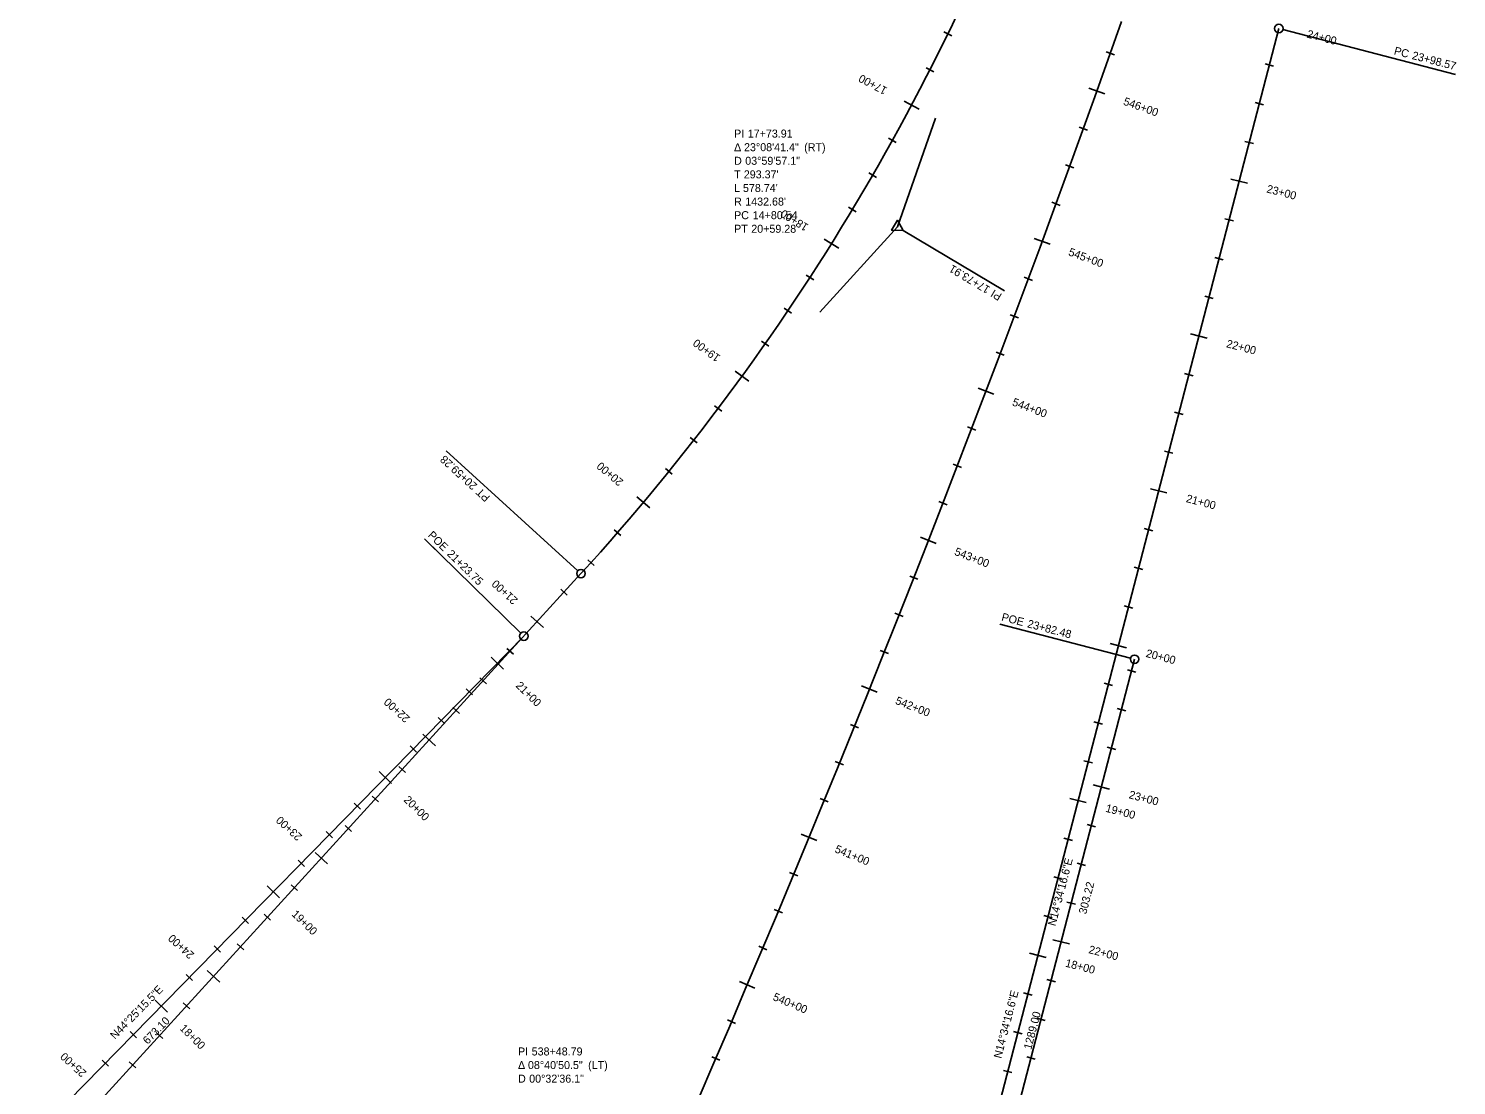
# Model space of a CAD drawing. Extents: x 2300830 to 2307917, y 756066 to 766359.
# Drawn here: x 2303759 to 2304651, y 762760 to 763421 of the extents above; entities that cross this region are included whole.
import ezdxf

# ---------------------------------------------------------------- set-up
doc = ezdxf.new("R2010")
doc.units = 0
for name, color, linetype in [('Default', 7, 'Continuous'), ('Draft_Bearing Label', 7, 'Continuous'), ('Draft_Curve Data Label', 7, 'Continuous'), ('Draft_Station Cardinal Lines', 7, 'Continuous'), ('Draft_Station Cardinal Points', 7, 'Continuous'), ('Draft_Station Labels Major', 7, 'Continuous'), ('Draft_Station Ticks Major', 7, 'Continuous'), ('Draft_Station Ticks Minor', 7, 'Continuous'), ('Geom_Baseline', 7, 'Continuous')]:
    doc.layers.add(name, color=color, linetype=linetype)

msp = doc.modelspace()

# ---------------------------------------------------------------- linework, layer by layer
at = {"layer": 'Default'}
for p, q in [((2304215.74, 762173.16), (2304540.03, 763420.7)), ((2304103.9, 763079.98), (2303443.21, 762356.01)), ((2303597.11, 762560.16), (2304068.23, 763040.89)), ((2304373.62, 762732.97), (2304449.9, 763026.43))]:
    msp.add_line(p, q, dxfattribs=at)
for centre, radius, start, end in [((2303045.65, 764045.73), 1432.68, 317.61666, 340.7615), ((2294501.04, 766942.01), 10544.55, 331.835697, 340.516399)]:
    msp.add_arc(centre, radius, start, end, dxfattribs=at)
at = {"layer": 'Draft_Station Cardinal Lines'}
for p, q in [((2304542.61, 763420.03), (2304650.36, 763392.02)), ((2304301.65, 763296.67), (2304325.38, 763364.65)), ((2304301.65, 763296.67), (2304253.12, 763243.49)), ((2304305.26, 763294.52), (2304368.64, 763256.72)), ((2304101.93, 763081.78), (2304019.69, 763156.82))]:
    msp.add_line(p, q, dxfattribs=at)
msp.add_lwpolyline([(2304305.22, 763294.55), (2304301.71, 763300.83), (2304298.02, 763294.65)], close=True, dxfattribs=at)
at = {"layer": 'Draft_Station Cardinal Points'}
for p, q in [((2304650.36, 763392.02), (2304650.36, 763392.02)), ((2304301.65, 763296.67), (2304301.65, 763296.67)), ((2304368.64, 763256.72), (2304368.64, 763256.72)), ((2304019.69, 763156.82), (2304019.69, 763156.82)), ((2304066.32, 763042.76), (2304006.09, 763101.79)), ((2304006.09, 763101.79), (2304020.15, 763088.01)), ((2304103.9, 763079.98), (2304103.9, 763079.98)), ((2304447.32, 763027.1), (2304365.7, 763048.32)), ((2304365.7, 763048.32), (2304384.75, 763043.36)), ((2304068.23, 763040.89), (2304068.23, 763040.89)), ((2304449.9, 763026.43), (2304449.9, 763026.43))]:
    msp.add_line(p, q, dxfattribs=at)
for centre in [(2304540.03, 763420.7), (2304103.9, 763079.98), (2304068.23, 763040.89), (2304449.9, 763026.43)]:
    msp.add_circle(centre, 2.67, dxfattribs=at)
at = {"layer": 'Draft_Station Ticks Major'}
for p, q in [((2304421.3, 763383.44), (2304431.3, 763379.86)), ((2304315.17, 763370.29), (2304305.79, 763375.28)), ((2304510.06, 763326.64), (2304520.34, 763323.97)), ((2304264.97, 763283.39), (2304255.96, 763289.02)), ((2304387.11, 763289.52), (2304397.07, 763285.84)), ((2304484.9, 763229.86), (2304495.18, 763227.18)), ((2304208.83, 763200.21), (2304200.24, 763206.46)), ((2304352.02, 763195.94), (2304361.95, 763192.16)), ((2304147.03, 763121.15), (2304138.9, 763127.97)), ((2304459.74, 763133.07), (2304470.02, 763130.4)), ((2304316.06, 763102.68), (2304325.95, 763098.81)), ((2304080.39, 763046.3), (2304072.55, 763053.46)), ((2304434.59, 763036.29), (2304444.86, 763033.62)), ((2304047.79, 763027.67), (2304055.38, 763020.24)), ((2304279.2, 763009.78), (2304289.06, 763005.81)), ((2304012.99, 762972.44), (2304005.14, 762979.59)), ((2303977.8, 762956.25), (2303985.39, 762948.81)), ((2304423.98, 762947.94), (2304434.26, 762945.27)), ((2304409.43, 762939.51), (2304419.71, 762936.83)), ((2304241.47, 762917.22), (2304251.29, 762913.17)), ((2303945.58, 762898.57), (2303937.73, 762905.73)), ((2303907.81, 762884.83), (2303915.39, 762877.39)), ((2304398.83, 762851.16), (2304409.1, 762848.49)), ((2304384.27, 762842.72), (2304394.55, 762840.05)), ((2303878.17, 762824.71), (2303870.32, 762831.86)), ((2304202.87, 762825.03), (2304212.64, 762820.88)), ((2303837.82, 762813.4), (2303845.4, 762805.97))]:
    msp.add_line(p, q, dxfattribs=at)
at = {"layer": 'Draft_Station Ticks Minor'}
for p, q in [((2304335.64, 763416.13), (2304330.68, 763418.55)), ((2304432.14, 763406.11), (2304437.34, 763404.26)), ((2304324.46, 763393.72), (2304319.54, 763396.22)), ((2304531.43, 763398.58), (2304536.77, 763397.19)), ((2304525.14, 763374.38), (2304530.48, 763372.99)), ((2304415.26, 763359.06), (2304420.45, 763357.18)), ((2304300.93, 763349.49), (2304296.1, 763352.17)), ((2304518.85, 763350.19), (2304524.19, 763348.8)), ((2304406.74, 763335.56), (2304411.93, 763333.67)), ((2304288.59, 763327.69), (2304283.81, 763330.45)), ((2304275.87, 763306.11), (2304271.14, 763308.96)), ((2304398.16, 763312.09), (2304403.34, 763310.18)), ((2304506.27, 763301.8), (2304511.61, 763300.41)), ((2304499.98, 763277.6), (2304505.32, 763276.21)), ((2304249.32, 763263.64), (2304244.69, 763266.65)), ((2304380.84, 763265.2), (2304386.01, 763263.27)), ((2304493.69, 763253.4), (2304499.03, 763252.01)), ((2304235.49, 763242.76), (2304230.91, 763245.84)), ((2304372.09, 763241.78), (2304377.26, 763239.85)), ((2304221.3, 763222.12), (2304216.77, 763225.28)), ((2304363.29, 763218.39), (2304368.46, 763216.44)), ((2304481.11, 763205.01), (2304486.45, 763203.62)), ((2304191.84, 763181.6), (2304187.43, 763184.92)), ((2304474.82, 763180.82), (2304480.16, 763179.43)), ((2304345.52, 763171.67), (2304350.68, 763169.69)), ((2304176.59, 763161.73), (2304172.24, 763165.13)), ((2304468.53, 763156.62), (2304473.87, 763155.23)), ((2304160.99, 763142.13), (2304156.7, 763145.6)), ((2304336.56, 763148.34), (2304341.71, 763146.35)), ((2304327.54, 763125.03), (2304332.68, 763123.03)), ((2304128.78, 763103.76), (2304124.62, 763107.38)), ((2304455.95, 763108.23), (2304461.29, 763106.84)), ((2304112.18, 763085.01), (2304108.08, 763088.7)), ((2304449.66, 763084.03), (2304455, 763082.64)), ((2304309.33, 763078.48), (2304314.46, 763076.45)), ((2304095.34, 763066.51), (2304091.26, 763070.23)), ((2304300.14, 763055.23), (2304305.27, 763053.2)), ((2304443.37, 763059.84), (2304448.71, 763058.45)), ((2304061.64, 763029.57), (2304057.56, 763033.29)), ((2304290.9, 763032.01), (2304296.02, 763029.96)), ((2304445.35, 763019.88), (2304450.69, 763018.49)), ((2304044.78, 763011.11), (2304040.71, 763014.83)), ((2304430.79, 763011.44), (2304436.14, 763010.06)), ((2304032.14, 763008.01), (2304036.08, 763004.14)), ((2304027.93, 762992.64), (2304023.85, 762996.36)), ((2304439.06, 762995.69), (2304444.4, 762994.3)), ((2304014.64, 762990.15), (2304018.58, 762986.29)), ((2304272.25, 762985.63), (2304277.36, 762983.56)), ((2304424.5, 762987.25), (2304429.85, 762985.86)), ((2303997.14, 762972.3), (2304001.08, 762968.43)), ((2304432.77, 762971.49), (2304438.11, 762970.1)), ((2303994.23, 762955.71), (2303990.15, 762959.43)), ((2304262.84, 762962.48), (2304267.95, 762960.4)), ((2304418.21, 762963.05), (2304423.56, 762961.66)), ((2303977.37, 762937.24), (2303973.3, 762940.96)), ((2304253.38, 762939.35), (2304258.48, 762937.25)), ((2303962.14, 762936.59), (2303966.09, 762932.72)), ((2303960.52, 762918.78), (2303956.45, 762922.5)), ((2304420.19, 762923.1), (2304425.53, 762921.71)), ((2303944.65, 762918.73), (2303948.59, 762914.87)), ((2304405.63, 762914.66), (2304410.98, 762913.27)), ((2303927.15, 762900.87), (2303931.09, 762897.01)), ((2304413.9, 762898.9), (2304419.24, 762897.51)), ((2303926.82, 762881.84), (2303922.74, 762885.56)), ((2304234.29, 762893.15), (2304239.38, 762891.03)), ((2304399.35, 762890.47), (2304404.69, 762889.08)), ((2304224.66, 762870.08), (2304229.75, 762867.95)), ((2304407.61, 762874.71), (2304412.96, 762873.32)), ((2303892.15, 762865.16), (2303896.09, 762861.3)), ((2303909.97, 762863.38), (2303905.89, 762867.1)), ((2304393.06, 762866.27), (2304398.4, 762864.88)), ((2303874.65, 762847.31), (2303878.6, 762843.45)), ((2303893.11, 762844.91), (2303889.04, 762848.63)), ((2304214.98, 762847.04), (2304220.06, 762844.9)), ((2303857.16, 762829.45), (2303861.1, 762825.59)), ((2304395.03, 762826.31), (2304400.38, 762824.93)), ((2304380.48, 762817.88), (2304385.82, 762816.49)), ((2303859.41, 762807.98), (2303855.33, 762811.7)), ((2304195.45, 762801.03), (2304200.53, 762798.86)), ((2304388.74, 762802.12), (2304394.09, 762800.73)), ((2303822.16, 762793.74), (2303826.1, 762789.88)), ((2303842.56, 762789.51), (2303838.48, 762793.23)), ((2304374.19, 762793.68), (2304379.53, 762792.29)), ((2303804.66, 762775.89), (2303808.6, 762772.02)), ((2303825.71, 762771.05), (2303821.63, 762774.77)), ((2304185.61, 762778.05), (2304190.68, 762775.87)), ((2304367.9, 762769.49), (2304373.24, 762768.1)), ((2304382.45, 762777.92), (2304387.8, 762776.53))]:
    msp.add_line(p, q, dxfattribs=at)
at = {"layer": 'Geom_Baseline'}
for p, q in [((2304215.74, 762173.16), (2304540.03, 763420.7)), ((2304103.9, 763079.98), (2303443.21, 762356.01)), ((2303597.11, 762560.16), (2304068.23, 763040.89)), ((2304373.62, 762732.97), (2304449.9, 763026.43))]:
    msp.add_line(p, q, dxfattribs=at)
for centre, radius, start, end in [((2303045.65, 764045.73), 1432.68, 317.61666, 340.7615), ((2294501.04, 766942.01), 10544.55, 331.835697, 340.516399)]:
    msp.add_arc(centre, radius, start, end, dxfattribs=at)

# ---------------------------------------------------------------- texts
at = {"layer": 'Draft_Bearing Label'}
for s, rotation, p in [('N14°34\'16.6"E', 75.42872, (2304400.4, 762859.37)), ('303.22', 75.42872, (2304419.65, 762866.8)), ('N44°25\'15.5"E', 45.57902, (2303812.7, 762788.55)), ('N14°34\'16.6"E', 75.42872, (2304366.52, 762776.6)), ('1289.00', 75.42872, (2304385.28, 762782.14)), ('673.10', 45.57902, (2303833.09, 762785.4))]:
    msp.add_text(s, height=5, rotation=rotation, dxfattribs=at).set_placement(p)
at = {"layer": 'Draft_Curve Data Label'}
for s, p in [('PI ', (2304199.58, 763352.55)), ('17+73.91', (2304208.12, 763352.55)), ('Δ ', (2304199.58, 763344.05)), ('D ', (2304199.58, 763335.55)), ('23°08\'41.4"', (2304205.8, 763344.05)), ('03°59\'57.1"', (2304206.56, 763335.55)), (' (RT)', (2304241.53, 763344.05)), ('T ', (2304199.58, 763327.05)), ("293.37'", (2304205.66, 763327.05)), ('L ', (2304199.58, 763318.55)), ("578.74'", (2304205.14, 763318.55)), ('R ', (2304199.58, 763310.05)), ("1432.68'", (2304206.56, 763310.05)), ('PC ', (2304199.58, 763301.55)), ('14+80.54', (2304211.22, 763301.55)), ('PT ', (2304199.58, 763293.05)), ('20+59.28', (2304210.32, 763293.05)), ('PI ', (2304064.55, 762778.81)), ('538+48.79', (2304073.09, 762778.81)), ('Δ ', (2304064.55, 762770.31)), ('08°40\'50.5"', (2304070.77, 762770.31)), (' (LT)', (2304106.5, 762770.31)), ('D ', (2304064.55, 762761.81)), ('00°32\'36.1"', (2304071.53, 762761.81))]:
    msp.add_text(s, height=5, dxfattribs=at).set_placement(p)
at = {"layer": 'Draft_Station Cardinal Points'}
for s, rotation, p in [('PC', 345.42872, (2304611.65, 763404.65)), ('23+98.57', 345.42872, (2304622.92, 763401.72)), ('17+73.91', 149.18908, (2304360.04, 763258.96)), ('PI ', 149.18908, (2304367.37, 763254.59)), ('20+59.28', 137.61666, (2304039.44, 763135.43)), ('PT', 137.61666, (2304047.47, 763128.11)), ('POE ', 315.57902, (2304007.83, 763103.56)), ('21+23.75', 315.57902, (2304019.76, 763091.88)), ('POE ', 345.42872, (2304366.33, 763050.72)), ('23+82.48', 345.42872, (2304382.49, 763046.52))]:
    msp.add_text(s, height=5, rotation=rotation, dxfattribs=at).set_placement(p)
at = {"layer": 'Draft_Station Labels Major'}
for s, rotation, p in [('24+00', 345.41448, (2304557.18, 763415.13)), ('17+00', 151.98504, (2304295.74, 763383.46)), ('546+00', 340.26621, (2304442.43, 763373.21)), ('23+00', 345.42872, (2304532.02, 763318.35)), ('18+00', 147.98585, (2304246.5, 763297.89)), ('545+00', 339.72285, (2304408.13, 763279.09)), ('19+00', 143.98665, (2304191.42, 763215.96)), ('22+00', 345.42872, (2304506.86, 763221.57)), ('544+00', 339.17948, (2304372.95, 763185.3)), ('20+00', 139.98745, (2304130.76, 763138.07)), ('21+00', 345.42872, (2304481.7, 763124.78)), ('543+00', 338.63611, (2304336.88, 763091.85)), ('21+00', 137.61666, (2304064.84, 763063.88)), ('20+00', 345.42872, (2304456.55, 763028)), ('21+00', 315.57902, (2304062.71, 763009.55)), ('22+00', 137.61666, (2303997.43, 762990.02)), ('542+00', 338.09274, (2304299.93, 762998.75)), ('20+00', 315.57902, (2303992.72, 762938.13)), ('23+00', 345.42872, (2304445.94, 762939.65)), ('19+00', 345.42872, (2304431.39, 762931.21)), ('23+00', 137.61666, (2303930.02, 762916.15)), ('541+00', 337.54937, (2304262.09, 762906)), ('19+00', 315.57902, (2303922.73, 762866.7)), ('24+00', 137.61666, (2303862.61, 762842.29)), ('22+00', 345.42872, (2304420.79, 762842.87)), ('18+00', 345.42872, (2304406.23, 762834.43)), ('540+00', 337.006, (2304223.38, 762813.61)), ('18+00', 315.57902, (2303852.74, 762795.28)), ('25+00', 137.61666, (2303795.2, 762768.42))]:
    msp.add_text(s, height=5, rotation=rotation, dxfattribs=at).set_placement(p)

doc.saveas('drawing.dxf')
